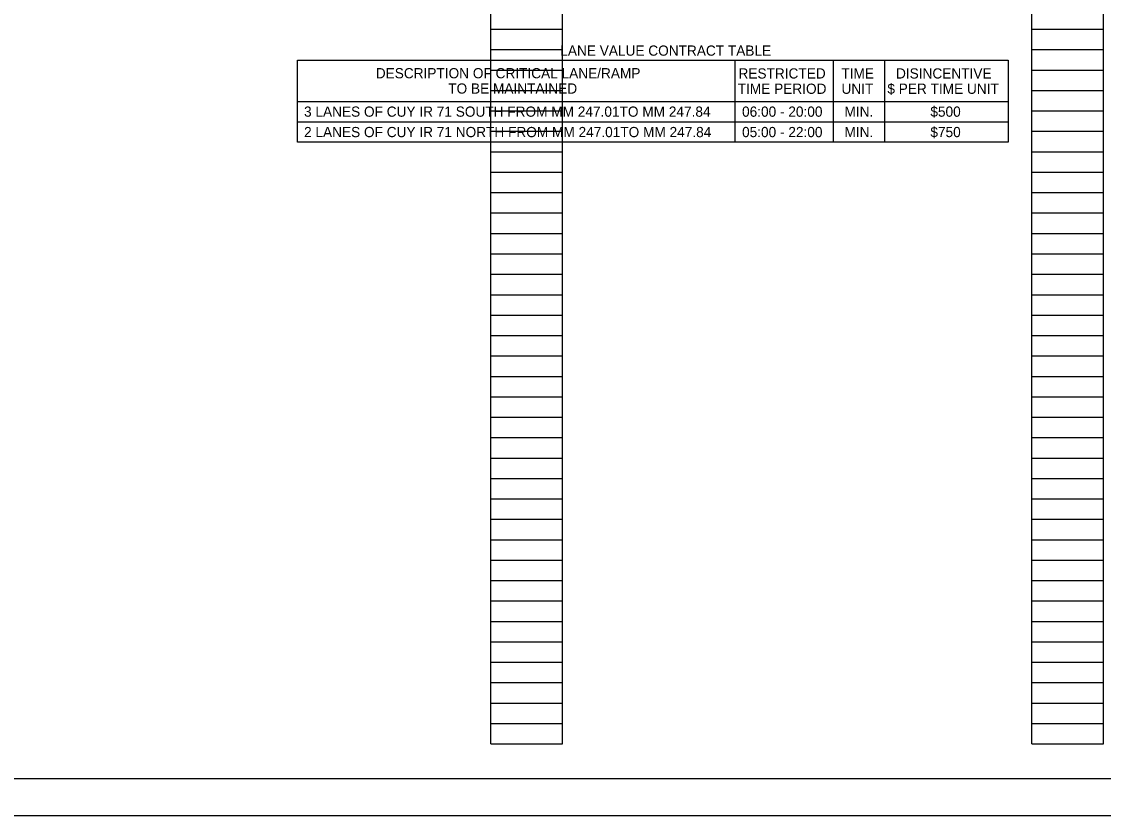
# Model space of a CAD drawing. Extents: x 0 to 43.6, y -18 to 22.
# Drawn here: x 9.82 to 24.66, y 0 to 10.88 of the extents above; entities that cross this region are included whole.
import ezdxf

# ---------------------------------------------------------------- set-up
doc = ezdxf.new("R2010")
doc.units = 0
for name, color, linetype in [('SH_Border', 7, 'Continuous'), ('SH_Cut_Line', 7, 'Continuous'), ('SH_Data', 7, 'Continuous'), ('SH_Major_Grid_Line', 7, 'Continuous'), ('SH_Minor_Grid_Line', 7, 'Continuous'), ('SH_Text', 7, 'Continuous')]:
    doc.layers.add(name, color=color, linetype=linetype)

msp = doc.modelspace()

# ---------------------------------------------------------------- linework, layer by layer
at = {"layer": 'SH_Border'}
msp.add_lwpolyline([(1.5, 21.5), (33.5, 21.5), (33.5, 0.5), (1.5, 0.5)], close=True, dxfattribs=at)
at = {"layer": 'SH_Cut_Line'}
msp.add_lwpolyline([(0, 0), (34, 0), (34, 22), (0, 22)], close=True, dxfattribs=at)
at = {"layer": 'SH_Data'}
for p, q in [((16.26, 0.98), (16.26, 21.14)), ((17.24, 0.98), (17.24, 21.14)), ((23.68, 0.98), (23.68, 21.14)), ((24.66, 0.98), (24.66, 21.14)), ((16.26, 10.78), (17.24, 10.78)), ((23.68, 10.78), (24.66, 10.78)), ((16.26, 10.5), (17.24, 10.5)), ((23.68, 10.5), (24.66, 10.5)), ((16.26, 10.22), (17.24, 10.22)), ((23.68, 10.22), (24.66, 10.22)), ((16.26, 9.94), (17.24, 9.94)), ((23.68, 9.94), (24.66, 9.94)), ((16.26, 9.66), (17.24, 9.66)), ((23.68, 9.66), (24.66, 9.66)), ((16.26, 9.38), (17.24, 9.38)), ((23.68, 9.38), (24.66, 9.38)), ((16.26, 9.1), (17.24, 9.1)), ((23.68, 9.1), (24.66, 9.1)), ((16.26, 8.82), (17.24, 8.82)), ((23.68, 8.82), (24.66, 8.82)), ((16.26, 8.54), (17.24, 8.54)), ((23.68, 8.54), (24.66, 8.54)), ((16.26, 8.26), (17.24, 8.26)), ((23.68, 8.26), (24.66, 8.26)), ((16.26, 7.98), (17.24, 7.98)), ((23.68, 7.98), (24.66, 7.98)), ((16.26, 7.7), (17.24, 7.7)), ((23.68, 7.7), (24.66, 7.7)), ((16.26, 7.42), (17.24, 7.42)), ((23.68, 7.42), (24.66, 7.42)), ((16.26, 7.14), (17.24, 7.14)), ((23.68, 7.14), (24.66, 7.14)), ((16.26, 6.86), (17.24, 6.86)), ((23.68, 6.86), (24.66, 6.86)), ((16.26, 6.58), (17.24, 6.58)), ((23.68, 6.58), (24.66, 6.58)), ((16.26, 6.3), (17.24, 6.3)), ((23.68, 6.3), (24.66, 6.3)), ((16.26, 6.02), (17.24, 6.02)), ((23.68, 6.02), (24.66, 6.02)), ((16.26, 5.74), (17.24, 5.74)), ((23.68, 5.74), (24.66, 5.74)), ((16.26, 5.46), (17.24, 5.46)), ((23.68, 5.46), (24.66, 5.46)), ((16.26, 5.18), (17.24, 5.18)), ((23.68, 5.18), (24.66, 5.18)), ((16.26, 4.9), (17.24, 4.9)), ((23.68, 4.9), (24.66, 4.9)), ((16.26, 4.62), (17.24, 4.62)), ((23.68, 4.62), (24.66, 4.62)), ((16.26, 4.34), (17.24, 4.34)), ((23.68, 4.34), (24.66, 4.34)), ((16.26, 4.06), (17.24, 4.06)), ((23.68, 4.06), (24.66, 4.06)), ((16.26, 3.78), (17.24, 3.78)), ((23.68, 3.78), (24.66, 3.78)), ((16.26, 3.5), (17.24, 3.5)), ((23.68, 3.5), (24.66, 3.5)), ((16.26, 3.22), (17.24, 3.22)), ((23.68, 3.22), (24.66, 3.22)), ((16.26, 2.94), (17.24, 2.94)), ((23.68, 2.94), (24.66, 2.94)), ((16.26, 2.66), (17.24, 2.66)), ((23.68, 2.66), (24.66, 2.66)), ((16.26, 2.38), (17.24, 2.38)), ((23.68, 2.38), (24.66, 2.38)), ((16.26, 2.1), (17.24, 2.1)), ((23.68, 2.1), (24.66, 2.1)), ((16.26, 1.82), (17.24, 1.82)), ((23.68, 1.82), (24.66, 1.82)), ((16.26, 1.54), (17.24, 1.54)), ((23.68, 1.54), (24.66, 1.54)), ((16.26, 1.26), (17.24, 1.26)), ((23.68, 1.26), (24.66, 1.26)), ((16.26, 0.98), (17.24, 0.98)), ((23.68, 0.98), (24.66, 0.98))]:
    msp.add_line(p, q, dxfattribs=at)
at = {"layer": 'SH_Major_Grid_Line'}
msp.add_lwpolyline([(13.606, 10.355), (23.356, 10.355), (23.356, 9.229), (13.606, 9.229)], close=True, dxfattribs=at)
at = {"layer": 'SH_Minor_Grid_Line'}
for p, q in [((19.606, 10.355), (19.606, 9.229)), ((20.956, 10.355), (20.956, 9.229)), ((21.656, 10.355), (21.656, 9.229)), ((13.606, 9.789), (23.356, 9.789)), ((13.606, 9.509), (23.356, 9.509))]:
    msp.add_line(p, q, dxfattribs=at)

# ---------------------------------------------------------------- texts
at = {"layer": 'SH_Text'}
for s, p in [('LANE VALUE CONTRACT TABLE', (17.211, 10.417)), ('DESCRIPTION OF CRITICAL LANE/RAMP', (14.68, 10.107)), ('RESTRICTED', (19.655, 10.104)), ('TIME', (21.067, 10.104)), ('DISINCENTIVE', (21.816, 10.104)), ('TO BE MAINTAINED', (15.674, 9.897)), ('TIME PERIOD', (19.645, 9.894)), ('UNIT', (21.068, 9.894)), ('$ PER TIME UNIT', (21.697, 9.894)), ('3 LANES OF CUY IR 71 SOUTH FROM MM 247.01TO MM 247.84', (13.696, 9.58)), ('06:00 - 20:00', (19.704, 9.58)), ('MIN.', (21.109, 9.58)), ('$500', (22.287, 9.58)), ('2 LANES OF CUY IR 71 NORTH FROM MM 247.01TO MM 247.84', (13.696, 9.3)), ('05:00 - 22:00', (19.704, 9.3)), ('MIN.', (21.109, 9.3)), ('$750', (22.287, 9.3))]:
    msp.add_text(s, height=0.14, dxfattribs=at).set_placement(p)

doc.saveas('drawing.dxf')
